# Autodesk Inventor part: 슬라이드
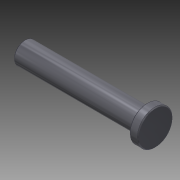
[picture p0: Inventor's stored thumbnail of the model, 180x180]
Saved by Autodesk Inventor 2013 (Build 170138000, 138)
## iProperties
Created: 2015-10
Part Number: 슬라이드
Document SubType Name: Modeling
Designer: mdu
Density: 1 g/cm^3
Material: 강철, 연강
Author: mdu
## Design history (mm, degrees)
sketch "스케치1"
  geometry: L1 (-75, 162)-(-75, 58) reference; L2 (-128, 110)-(22, 110); L3 (-128, 110)-(-128, 122.5); L4 (-128, 122.5)-(12, 122.5); L5 (12, 122.5)-(12, 130); L6 (12, 130)-(22, 130); L7 (22, 130)-(22, 110); 2 further points
  constraints: 12 end point, 3 parallel, 3 perpendicular, 1 midpoint, 1 point on line
  dimensions: "d0" = 40 diameter of L6 L2; "d1" = 25 diameter of L4 L2; "d2" = 10 distance of L5.end L6.end; "d3" = 150 distance of L2.start L2.end; "d4" = 53 distance between parallel lines of L3 L1
revolve "회전1" sketch "스케치1" stored, may be unused: angle "d5" = 90 deg
hole "구멍1" diameter "d11" = 10.106; stored, may be unused: countersink angle "d15" = 90 deg, drill point angle "d17" = 118 deg; dims "d12" = 22, "d13" = 4, "d14" = 2, "d16" = 25, "d18" = 10, "d19" = 10
chamfer "모따기1" distance "d6" = 1; stored, may be unused: second distance "d7" = 2, angle "d8" = 45 deg
node "솔리드1"
node "참조1"
